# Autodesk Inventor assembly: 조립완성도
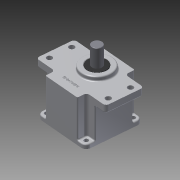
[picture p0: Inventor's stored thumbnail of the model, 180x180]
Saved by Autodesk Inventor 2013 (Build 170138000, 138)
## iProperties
Created: 2015-07
Part Number: 조립완성도
Document SubType Name: Assembly
Designer: user
Author: user
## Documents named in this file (11)
- C:\Users\user\Desktop\450734V1003\조립완성도.iam
- C:\Users\user\Desktop\450734V1003\메인축.ipt
- C:\Users\user\Desktop\450734V1003\베어링 608.ipt
- 베어링 608.ipt
- C:\Users\user\Desktop\450734V1003\본체.ipt
- C:\Users\user\Desktop\450734V1003\서브축.ipt
- C:\Users\user\Desktop\450734V1003\베어링 6003.ipt
- 베어링 6003.ipt
- C:\Users\user\Desktop\450734V1003\오일실 17x32x8.ipt
- C:\Users\user\Desktop\450734V1003\커버.ipt
- C:\Users\user\Desktop\450734V1003\오일실 8x22x7.ipt
